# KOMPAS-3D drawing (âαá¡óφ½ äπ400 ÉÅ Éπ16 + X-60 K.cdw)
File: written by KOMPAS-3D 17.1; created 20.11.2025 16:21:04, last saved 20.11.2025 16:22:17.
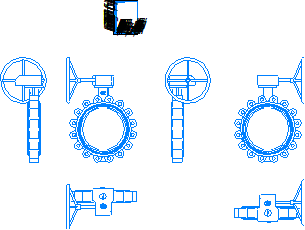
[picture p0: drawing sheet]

Sheet 1: A4, portrait

Title block, sheet 1: name: Гранвэл Ду400; material: Сталь 10  ГОСТ 1050-88; mass: 258,37; sheets: 1; sheet format: A4

Views: Проекционный вид 2, Проекционный вид 3, Проекционный вид 4, Проекционный вид 6
Referenced files in \\adlc.lan\data\АДЛ_ПКД\3D-модели\ADL production\Дисковые поворотные затворы ГРАНВЭЛ\с резьбовыми проушинами с китайским редуктором Ру 16\KOMPAS 3D\: Гранвэл Ду400 РП Ру16 + X-60 K.m3d
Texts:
  Andrey
  АДЛ
Dimensions and other numbers on the sheet: 1:1; 1; 258,37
